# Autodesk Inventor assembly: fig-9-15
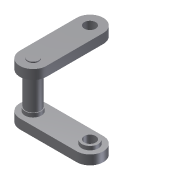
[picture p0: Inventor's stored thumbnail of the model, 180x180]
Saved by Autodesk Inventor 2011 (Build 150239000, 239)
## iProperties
Shininess: 64.0
Length Units: 11269
Angle Units: 11279
Time Units: 11290
Mass Units: 11283
Length Display Precision: 3
Angle Display Precision: 2
Created: 2002-01
Part Number: fig-9-15
Document SubType Name: Assembly
Designer: ***
Density: 0.0
Volumn: 0.0
Area: 0.0
PropertySet Name: Model Information
Control State: 0
Master: False
Checked Out: False
Author: ***
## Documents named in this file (3)
- C:\Users\CADSoft\Desktop\part files\c09-inv-2011-prt\fig-9-15.iam
- C:\Users\CADSoft\Desktop\inventor\c09-inv-2010-prt\c09\Part5.ipt
- C:\Users\CADSoft\Desktop\inventor\c09-inv-2010-prt\c09\Part6.ipt
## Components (3 placed, 2 different names)
1. Part5:1 — Insert:1, Angle:1
2. Part6:1 — Insert:1, Insert:2
3. Part5:2 — Insert:2, Angle:1
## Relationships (3: Insert 2, Angle 1)
- Insert:1: Part5:1 ↔ Part6:1
- Insert:2: Part6:1 ↔ Part5:2
- Angle:1: Part5:1 ↔ Part5:2
